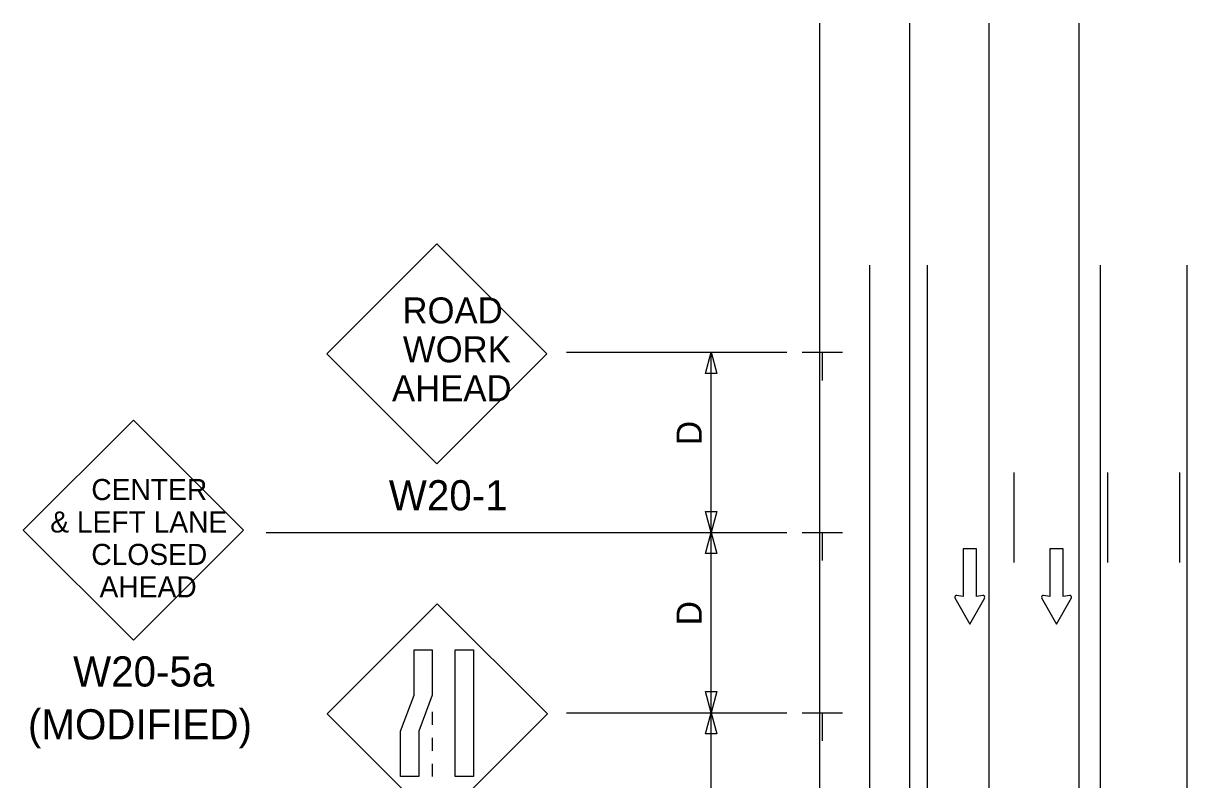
# Model space of a CAD drawing. Extents: x 16735 to 18475, y 6983 to 8262.
# Drawn here: x 16742.2 to 17065.1, y 8052.4 to 8262.3 of the extents above; entities that cross this region are included whole.
import ezdxf

# ---------------------------------------------------------------- set-up
doc = ezdxf.new("R2010")
doc.units = 0
for name, color, linetype in [('ALI_LEGAL_EX', 7, 'Continuous'), ('MT_SCRATCH_LEVEL_E', 7, 'Continuous'), ('PAVT_EDGE_EX', 7, 'Continuous'), ('TRAFFIC_SIGNS_PR', 7, 'Continuous'), ('TYPICAL_TEXT_DIMEN_PR', 7, 'Continuous')]:
    doc.layers.add(name, color=color, linetype=linetype)

msp = doc.modelspace()

# ---------------------------------------------------------------- linework, layer by layer
at = {"layer": 'ALI_LEGAL_EX'}
for points in [[(17017.08, 8137.7), (17017.08, 8112.7)], [(17043.08, 8137.7), (17043.08, 8112.7)], [(17063.08, 8137.7), (17063.08, 8112.7)]]:
    msp.add_lwpolyline(points, dxfattribs=at)
at = {"layer": 'MT_SCRATCH_LEVEL_E'}
for p, q in [((17006.75, 8116.49), (17003.01, 8116.49)), ((17003.01, 8116.49), (17003.01, 8103.24)), ((17006.75, 8116.49), (17003.01, 8116.49)), ((17003.01, 8116.49), (17003.01, 8103.24)), ((17006.75, 8103.24), (17006.75, 8116.49)), ((17006.75, 8103.24), (17006.75, 8116.49)), ((17030.82, 8116.49), (17027.08, 8116.49)), ((17027.08, 8116.49), (17027.08, 8103.24)), ((17030.82, 8116.49), (17027.08, 8116.49)), ((17027.08, 8116.49), (17027.08, 8103.24)), ((17030.82, 8103.24), (17030.82, 8116.49)), ((17030.82, 8103.24), (17030.82, 8116.49)), ((17000.75, 8102.87), (17004.9, 8095.63)), ((17000.75, 8102.87), (17004.9, 8095.63)), ((17003.01, 8103.24), (17001.23, 8103.55)), ((17003.01, 8103.24), (17001.23, 8103.55)), ((17004.9, 8095.63), (17009.01, 8102.87)), ((17004.9, 8095.63), (17009.01, 8102.87)), ((17008.53, 8103.55), (17006.75, 8103.24)), ((17008.53, 8103.55), (17006.75, 8103.24)), ((17024.82, 8102.87), (17028.97, 8095.63)), ((17024.82, 8102.87), (17028.97, 8095.63)), ((17027.08, 8103.24), (17025.3, 8103.55)), ((17027.08, 8103.24), (17025.3, 8103.55)), ((17028.97, 8095.63), (17033.08, 8102.87)), ((17028.97, 8095.63), (17033.08, 8102.87)), ((17032.6, 8103.55), (17030.82, 8103.24)), ((17032.6, 8103.55), (17030.82, 8103.24))]:
    msp.add_line(p, q, dxfattribs=at)
for centre, start, end in [((17001.16, 8103.09), 80.0362, 209.7731), ((17001.16, 8103.09), 80.0362, 209.7731), ((17008.6, 8103.09), 330.4248, 99.9638), ((17008.6, 8103.09), 330.4248, 99.9638), ((17025.23, 8103.09), 80.0362, 209.7731), ((17025.23, 8103.09), 80.0362, 209.7731), ((17032.67, 8103.09), 330.4248, 99.9638), ((17032.67, 8103.09), 330.4248, 99.9638)]:
    msp.add_arc(centre, 0.463, start, end, dxfattribs=at)
at = {"layer": 'PAVT_EDGE_EX'}
for p, q in [((16963.15, 8262.34), (16963.15, 7433.15)), ((16988.15, 8262.34), (16988.15, 7433.15)), ((17010.15, 8262.34), (17010.15, 7433.15)), ((17035.15, 8262.34), (17035.15, 7433.15)), ((16977.08, 8195.21), (16977.08, 7357.91)), ((16993.08, 8195.21), (16993.08, 7357.91)), ((17041.08, 8195.21), (17041.08, 7357.91)), ((17065.08, 8195.21), (17065.08, 7357.91))]:
    msp.add_line(p, q, dxfattribs=at)
at = {"layer": 'TRAFFIC_SIGNS_PR'}
for p, q in [((16856.97, 8201.13), (16826.42, 8170.59)), ((16887.51, 8170.59), (16856.97, 8201.13)), ((16826.42, 8170.59), (16856.97, 8140.04)), ((16856.97, 8140.04), (16887.51, 8170.59)), ((16772.77, 8152.24), (16742.23, 8121.69)), ((16803.32, 8121.69), (16772.77, 8152.24)), ((16742.23, 8121.69), (16772.77, 8091.14)), ((16772.77, 8091.14), (16803.32, 8121.69)), ((16857.12, 8101.27), (16826.58, 8070.72)), ((16887.67, 8070.72), (16857.12, 8101.27)), ((16826.58, 8070.72), (16857.12, 8040.17)), ((16855.72, 8071.27), (16855.72, 8067.67)), ((16857.12, 8040.17), (16887.67, 8070.72)), ((16855.72, 8064.07), (16855.72, 8060.47)), ((16855.72, 8056.87), (16855.72, 8053.27))]:
    msp.add_line(p, q, dxfattribs=at)
for points in [[(16855.72, 8088.43), (16855.72, 8075.85), (16851.96, 8065.85), (16851.96, 8053.27), (16846.9, 8053.27), (16846.9, 8065.85), (16850.67, 8075.85), (16850.67, 8088.43)], [(16867.12, 8088.43), (16867.12, 8053.27), (16862.07, 8053.27), (16862.07, 8088.43)]]:
    msp.add_lwpolyline(points, close=True, dxfattribs=at)
at = {"layer": 'TYPICAL_TEXT_DIMEN_PR'}
for p, q in [((16892.99, 8171.02), (16954.08, 8171.02)), ((16931.51, 8165.16), (16933.08, 8171.02)), ((16933.08, 8171.02), (16934.65, 8165.16)), ((16933.08, 8121.02), (16933.08, 8171.02)), ((16958.33, 8171.02), (16969.58, 8171.02)), ((16963.96, 8171.02), (16963.96, 8163.24)), ((16933.08, 8165.16), (16931.51, 8165.16)), ((16934.65, 8165.16), (16933.08, 8165.16)), ((16933.08, 8121.02), (16931.51, 8126.89)), ((16931.51, 8126.89), (16933.08, 8126.89)), ((16933.08, 8126.89), (16934.65, 8126.89)), ((16934.65, 8126.89), (16933.08, 8121.02)), ((16809.67, 8121.02), (16954.08, 8121.02)), ((16931.51, 8115.16), (16933.08, 8121.02)), ((16933.08, 8121.02), (16934.65, 8115.16)), ((16933.08, 8071.02), (16933.08, 8121.02)), ((16958.33, 8121.02), (16969.58, 8121.02)), ((16963.96, 8121.02), (16963.96, 8113.24)), ((16933.08, 8115.16), (16931.51, 8115.16)), ((16934.65, 8115.16), (16933.08, 8115.16)), ((16933.08, 8071.02), (16931.51, 8076.89)), ((16931.51, 8076.89), (16933.08, 8076.89)), ((16933.08, 8076.89), (16934.65, 8076.89)), ((16934.65, 8076.89), (16933.08, 8071.02)), ((16892.99, 8071.02), (16954.08, 8071.02)), ((16931.51, 8065.16), (16933.08, 8071.02)), ((16933.08, 8021.02), (16933.08, 8071.02)), ((16933.08, 8071.02), (16934.65, 8065.16)), ((16958.33, 8071.02), (16969.58, 8071.02)), ((16963.96, 8071.02), (16963.96, 8063.24)), ((16933.08, 8065.16), (16931.51, 8065.16)), ((16934.65, 8065.16), (16933.08, 8065.16))]:
    msp.add_line(p, q, dxfattribs=at)

# ---------------------------------------------------------------- texts
at = {"layer": 'TRAFFIC_SIGNS_PR'}
for s, height, p in [('ROAD', 7.2, (16847.45, 8179.06)), ('WORK', 7.2, (16847.57, 8168.26)), ('AHEAD', 7.2, (16844.55, 8157.46)), ('CENTER', 5.85, (16761.11, 8130.02)), ('W20-1', 8.37, (16843.66, 8127.17)), ('& LEFT LANE', 5.85, (16749.71, 8121.02)), ('CLOSED', 5.85, (16761.11, 8112.02)), ('AHEAD', 5.85, (16763.39, 8103.02)), ('W20-5a', 8.37, (16756.05, 8078.28)), ('(MODIFIED)', 8.37, (16743.52, 8063.61))]:
    msp.add_text(s, height=height, dxfattribs=at).set_placement(p)
at = {"layer": 'TYPICAL_TEXT_DIMEN_PR'}
for p in [(16930.52, 8145.24), (16930.52, 8095.24)]:
    msp.add_text('D', height=7, rotation=90, dxfattribs=at).set_placement(p)

doc.saveas('drawing.dxf')
